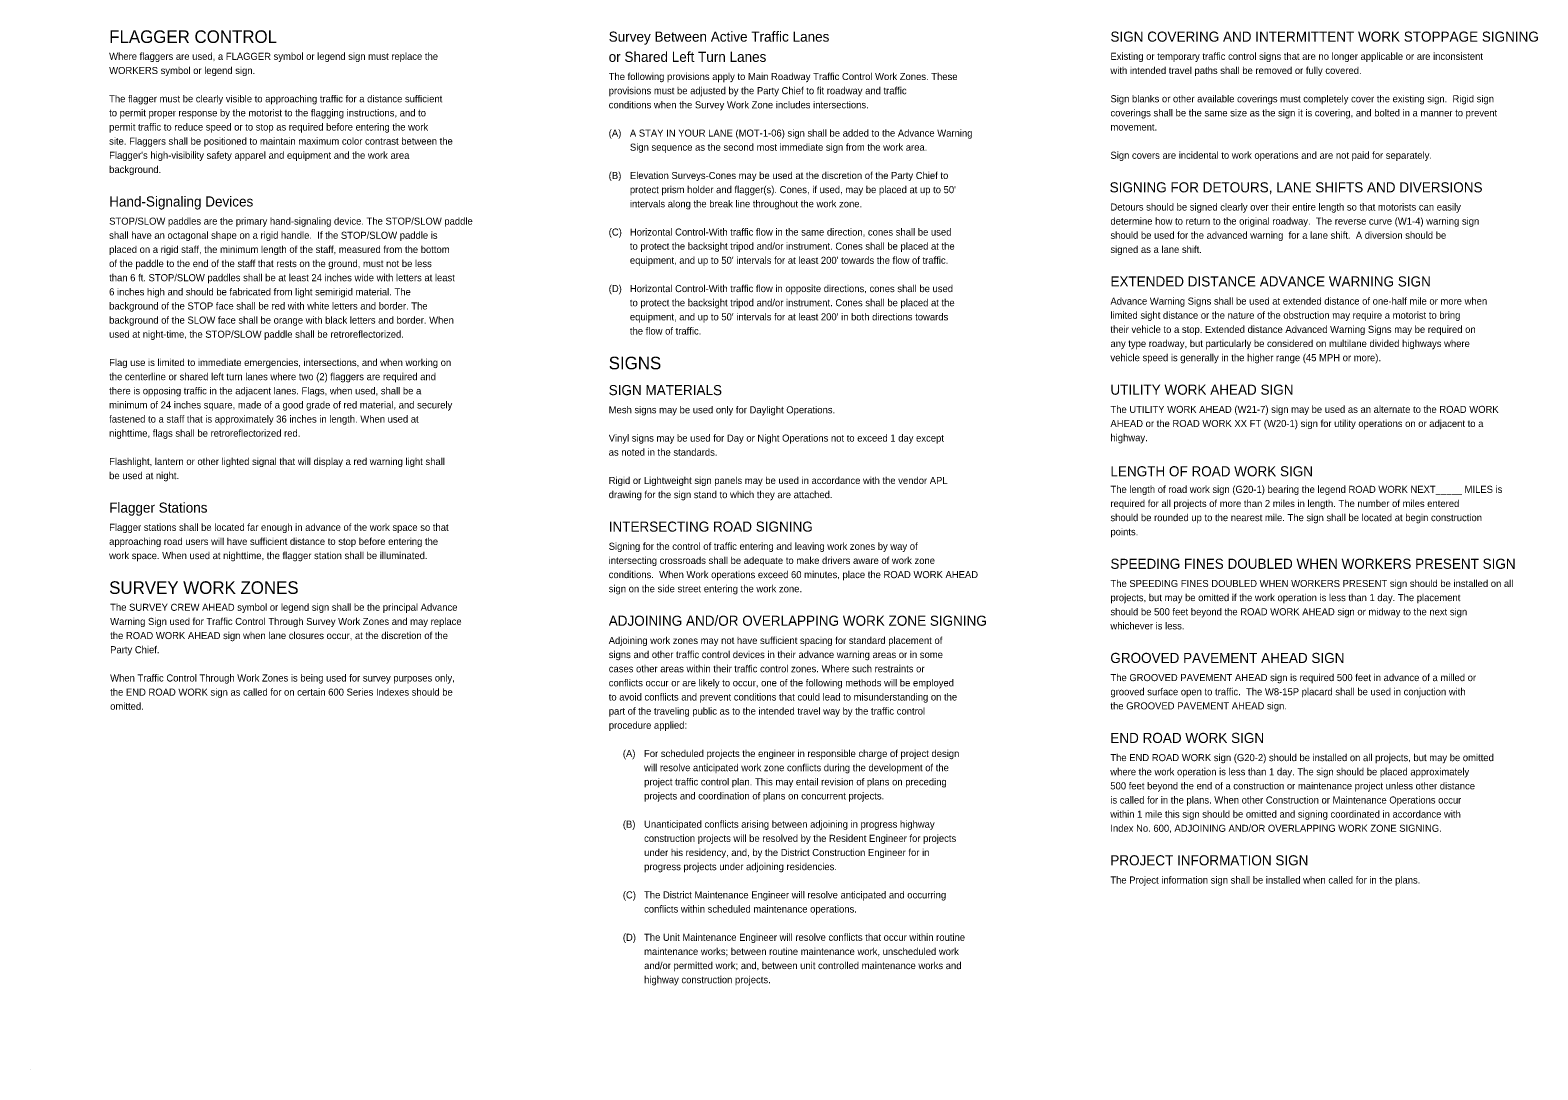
# Model space of a CAD drawing. Extents: x 10000 to 10746, y 10000 to 10515.
import ezdxf

# ---------------------------------------------------------------- set-up
doc = ezdxf.new("R2010")
doc.units = 0
doc.layers.add('Patterning', color=7, linetype='Continuous')
doc.layers.add('TextMisc', color=7, linetype='Continuous')

msp = doc.modelspace()

# ---------------------------------------------------------------- linework, layer by layer
at = {"layer": 'Patterning'}
msp.add_line((10000, 10000), (10000, 10000), dxfattribs=at)
msp.add_line((10000, 10000), (10000, 10000), dxfattribs=at)

# ---------------------------------------------------------------- texts
at = {"layer": 'TextMisc'}
for s, height, p in [('FLAGGER CONTROL', 6.25, (10039.11, 10508.47)), ('Survey Between Active Traffic Lanes', 5, (10286.45, 10509.1)), ('SIGN COVERING AND INTERMITTENT WORK STOPPAGE SIGNING', 5, (10534.87, 10509.1)), ('Where flaggers are used, a FLAGGER symbol or legend sign must replace the ', 3.5, (10039.11, 10500.1)), ('or Shared Left Turn Lanes', 5, (10286.45, 10499.1)), ('Existing or temporary traffic control signs that are no longer applicable or are inconsistent ', 3.5, (10534.87, 10500.1)), ('WORKERS symbol or legend sign.', 3.5, (10039.11, 10493.1)), ('with intended travel paths shall be removed or fully covered. ', 3.5, (10534.87, 10493.1)), ('The following provisions apply to Main Roadway Traffic Control Work Zones. These ', 3.5, (10286.45, 10490.1)), ('The flagger must be clearly visible to approaching traffic for a distance sufficient ', 3.5, (10039.11, 10479.1)), ('provisions must be adjusted by the Party Chief to fit roadway and traffic ', 3.5, (10286.45, 10483.1)), ('Sign blanks or other available coverings must completely cover the existing sign.  Rigid sign ', 3.5, (10534.87, 10479.1)), ('to permit proper response by the motorist to the flagging instructions, and to ', 3.5, (10039.11, 10472.1)), ('conditions when the Survey Work Zone includes intersections.', 3.5, (10286.45, 10476.1)), ('coverings shall be the same size as the sign it is covering, and bolted in a manner to prevent ', 3.5, (10534.87, 10472.1)), ('permit traffic to reduce speed or to stop as required before entering the work ', 3.5, (10039.11, 10465.1)), ('(A)', 3.5, (10286.45, 10462.1)), ('A STAY IN YOUR LANE (MOT-1-06) sign shall be added to the Advance Warning ', 3.5, (10296.95, 10462.1)), ('movement.', 3.5, (10534.87, 10465.1)), ('site. Flaggers shall be positioned to maintain maximum color contrast between the ', 3.5, (10039.11, 10458.1)), ('Sign sequence as the second most immediate sign from the work area.', 3.5, (10296.95, 10455.1)), ("Flagger's high-visibility safety apparel and equipment and the work area ", 3.5, (10039.11, 10451.1)), ('Sign covers are incidental to work operations and are not paid for separately.', 3.5, (10534.87, 10451.1)), ('background.', 3.5, (10039.11, 10444.1)), ('(B)', 3.5, (10286.45, 10441.1)), ('Elevation Surveys-Cones may be used at the discretion of the Party Chief to ', 3.5, (10296.95, 10441.1)), ("protect prism holder and flagger(s). Cones, if used, may be placed at up to 50'  ", 3.5, (10296.95, 10434.1)), ('SIGNING FOR DETOURS, LANE SHIFTS AND DIVERSIONS', 5, (10534.48, 10434.49)), ('Hand-Signaling Devices', 5, (10039.11, 10427.49)), ('intervals along the break line throughout the work zone.', 3.5, (10296.95, 10427.1)), ('Detours should be signed clearly over their entire length so that motorists can easily ', 3.5, (10534.87, 10425.49)), ('STOP/SLOW paddles are the primary hand-signaling device. The STOP/SLOW paddle ', 3.5, (10039.11, 10418.49)), ('determine how to return to the original roadway.  The reverse curve (W1-4) warning sign ', 3.5, (10534.87, 10418.49)), ('shall have an octagonal shape on a rigid handle.  If the STOP/SLOW paddle is ', 3.5, (10039.11, 10411.49)), ('(C)', 3.5, (10286.45, 10413.1)), ('Horizontal Control-With traffic flow in the same direction, cones shall be used ', 3.5, (10296.95, 10413.1)), ('should be used for the advanced warning  for a lane shift.  A diversion should be ', 3.5, (10534.87, 10411.49)), ('placed on a rigid staff, the minimum length of the staff, measured from the bottom ', 3.5, (10039.11, 10404.49)), ('to protect the backsight tripod and/or instrument. Cones shall be placed at the ', 3.5, (10296.95, 10406.1)), ('signed as a lane shift.', 3.5, (10534.87, 10404.49)), ('of the paddle to the end of the staff that rests on the ground, must not be less ', 3.5, (10039.11, 10397.49)), ("equipment, and up to 50' intervals for at least 200' towards the flow of traffic.", 3.5, (10296.95, 10399.1)), ('than 6 ft. STOP/SLOW paddles shall be at least 24 inches wide with letters at least ', 3.5, (10039.11, 10390.49)), ('EXTENDED DISTANCE ADVANCE WARNING SIGN', 5, (10534.87, 10387.89)), ('6 inches high and should be fabricated from light semirigid material. The ', 3.5, (10039.11, 10383.49)), ('(D)', 3.5, (10286.45, 10385.1)), ('Horizontal Control-With traffic flow in opposite directions, cones shall be used ', 3.5, (10296.95, 10385.1)), ('background of the STOP face shall be red with white letters and border. The ', 3.5, (10039.11, 10376.49)), ('to protect the backsight tripod and/or instrument. Cones shall be placed at the ', 3.5, (10296.95, 10378.1)), ('Advance Warning Signs shall be used at extended distance of one-half mile or more when ', 3.5, (10534.87, 10378.89)), ('background of the SLOW face shall be orange with black letters and border. When ', 3.5, (10039.11, 10369.49)), ("equipment, and up to 50' intervals for at least 200' in both directions towards ", 3.5, (10296.95, 10371.1)), ('limited sight distance or the nature of the obstruction may require a motorist to bring ', 3.5, (10534.87, 10371.89)), ('used at night-time, the STOP/SLOW paddle shall be retroreflectorized.', 3.5, (10039.11, 10362.49)), ('the flow of traffic.', 3.5, (10296.95, 10364.1)), ('their vehicle to a stop. Extended distance Advanced Warning Signs may be required on ', 3.5, (10534.87, 10364.89)), ('any type roadway, but particularly be considered on multilane divided highways where ', 3.5, (10534.87, 10357.89)), ('vehicle speed is generally in the higher range (45 MPH or more).', 3.5, (10534.87, 10350.89)), ('Flag use is limited to immediate emergencies, intersections, and when working on ', 3.5, (10039.11, 10348.49)), ('SIGNS', 6.25, (10286.45, 10346.87)), ('the centerline or shared left turn lanes where two (2) flaggers are required and ', 3.5, (10039.11, 10341.49)), ('SIGN MATERIALS', 5, (10286.45, 10334.08)), ('UTILITY WORK AHEAD SIGN', 5, (10534.87, 10334.29)), ('there is opposing traffic in the adjacent lanes. Flags, when used, shall be a ', 3.5, (10039.11, 10334.49)), ('fastened to a staff that is approximately 36 inches in length. When used at ', 3.5, (10039.11, 10320.49)), ('minimum of 24 inches square, made of a good grade of red material, and securely ', 3.5, (10039.11, 10327.49)), ('Mesh signs may be used only for Daylight Operations.', 3.5, (10286.45, 10325.08)), ('The UTILITY WORK AHEAD (W21-7) sign may be used as an alternate to the ROAD WORK ', 3.5, (10534.87, 10325.29)), ('nighttime, flags shall be retroreflectorized red.', 3.5, (10039.11, 10313.49)), ('AHEAD or the ROAD WORK XX FT (W20-1) sign for utility operations on or adjacent to a ', 3.5, (10534.87, 10318.29)), ('Vinyl signs may be used for Day or Night Operations not to exceed 1 day except ', 3.5, (10286.45, 10311.08)), ('highway.', 3.5, (10534.87, 10311.29)), ('Flashlight, lantern or other lighted signal that will display a red warning light shall ', 3.5, (10039.11, 10299.49)), ('as noted in the standards.', 3.5, (10286.45, 10304.08)), ('be used at night.', 3.5, (10039.11, 10292.49)), ('LENGTH OF ROAD WORK SIGN', 5, (10534.87, 10293.89)), ('drawing for the sign stand to which they are attached.', 3.5, (10286.45, 10283.08)), ('Rigid or Lightweight sign panels may be used in accordance with the vendor APL ', 3.5, (10286.45, 10290.08)), ('The length of road work sign (G20-1) bearing the legend ROAD WORK NEXT_____ MILES is ', 3.5, (10534.87, 10285.69)), ('Flagger Stations', 5, (10039.11, 10275.89)), ('required for all projects of more than 2 miles in length. The number of miles entered ', 3.5, (10534.87, 10278.69)), ('should be rounded up to the nearest mile. The sign shall be located at begin construction ', 3.5, (10534.87, 10271.69)), ('Flagger stations shall be located far enough in advance of the work space so that ', 3.5, (10039.11, 10266.89)), ('INTERSECTING ROAD SIGNING', 5, (10286.45, 10266.48)), ('points.', 3.5, (10534.87, 10264.69)), ('approaching road users will have sufficient distance to stop before entering the ', 3.5, (10039.11, 10259.89)), ('Signing for the control of traffic entering and leaving work zones by way of ', 3.5, (10286.45, 10257.48)), ('work space. When used at nighttime, the flagger station shall be illuminated.', 3.5, (10039.11, 10252.89)), ('intersecting crossroads shall be adequate to make drivers aware of work zone ', 3.5, (10286.45, 10250.48)), ('SPEEDING FINES DOUBLED WHEN WORKERS PRESENT SIGN', 5, (10534.87, 10248.08)), ('SURVEY WORK ZONES', 6.25, (10039.11, 10235.66)), ('conditions.  When Work operations exceed 60 minutes, place the ROAD WORK AHEAD ', 3.5, (10286.45, 10243.48)), ('The SPEEDING FINES DOUBLED WHEN WORKERS PRESENT sign should be installed on all ', 3.5, (10534.87, 10239.08)), ('sign on the side street entering the work zone.', 3.5, (10286.45, 10236.48)), ('projects, but may be omitted if the work operation is less than 1 day. The placement ', 3.5, (10534.87, 10232.08)), ('The SURVEY CREW AHEAD symbol or legend sign shall be the principal Advance ', 3.5, (10039.61, 10227.29)), ('should be 500 feet beyond the ROAD WORK AHEAD sign or midway to the next sign ', 3.5, (10534.87, 10225.08)), ('Warning Sign used for Traffic Control Through Survey Work Zones and may replace ', 3.5, (10039.61, 10220.29)), ('ADJOINING AND/OR OVERLAPPING WORK ZONE SIGNING', 5, (10286.45, 10219.88)), ('whichever is less. ', 3.5, (10534.87, 10218.08)), ('the ROAD WORK AHEAD sign when lane closures occur, at the discretion of the ', 3.5, (10039.61, 10213.29)), ('Adjoining work zones may not have sufficient spacing for standard placement of ', 3.5, (10286.45, 10210.88)), ('Party Chief. ', 3.5, (10039.61, 10206.29)), ('signs and other traffic control devices in their advance warning areas or in some ', 3.5, (10286.48, 10203.88)), ('GROOVED PAVEMENT AHEAD SIGN', 5, (10534.81, 10201.46)), ('cases other areas within their traffic control zones. Where such restraints or ', 3.5, (10286.48, 10196.88)), ('When Traffic Control Through Work Zones is being used for survey purposes only, ', 3.5, (10039.61, 10192.29)), ('conflicts occur or are likely to occur, one of the following methods will be employed ', 3.5, (10286.48, 10189.88)), ('The GROOVED PAVEMENT AHEAD sign is required 500 feet in advance of a milled or ', 3.5, (10534.87, 10192.48)), ('the END ROAD WORK sign as called for on certain 600 Series Indexes should be ', 3.5, (10039.61, 10185.29)), ('to avoid conflicts and prevent conditions that could lead to misunderstanding on the ', 3.5, (10286.48, 10182.88)), ('the GROOVED PAVEMENT AHEAD sign.', 3.5, (10534.87, 10178.48)), ('grooved surface open to traffic.  The W8-15P placard shall be used in conjuction with ', 3.5, (10534.87, 10185.48)), ('omitted.', 3.5, (10039.61, 10178.29)), ('part of the traveling public as to the intended travel way by the traffic control ', 3.5, (10286.48, 10175.88)), ('procedure applied:', 3.5, (10286.48, 10168.88)), ('END ROAD WORK SIGN', 5, (10534.81, 10161.86)), ('(A)', 3.5, (10293.45, 10154.88)), ('For scheduled projects the engineer in responsible charge of project design ', 3.5, (10303.95, 10154.88)), ('The END ROAD WORK sign (G20-2) should be installed on all projects, but may be omitted ', 3.5, (10534.81, 10152.86)), ('will resolve anticipated work zone conflicts during the development of the ', 3.5, (10303.98, 10147.88)), ('where the work operation is less than 1 day. The sign should be placed approximately ', 3.5, (10534.81, 10145.86)), ('project traffic control plan. This may entail revision of plans on preceding ', 3.5, (10303.98, 10140.88)), ('projects and coordination of plans on concurrent projects.', 3.5, (10303.98, 10133.88)), ('500 feet beyond the end of a construction or maintenance project unless other distance ', 3.5, (10534.81, 10138.86)), ('is called for in the plans. When other Construction or Maintenance Operations occur ', 3.5, (10534.81, 10131.86)), ('(B)', 3.5, (10293.45, 10119.88)), ('Unanticipated conflicts arising between adjoining in progress highway ', 3.5, (10303.95, 10119.88)), ('within 1 mile this sign should be omitted and signing coordinated in accordance with ', 3.5, (10534.81, 10124.86)), ('construction projects will be resolved by the Resident Engineer for projects ', 3.5, (10303.98, 10112.88)), ('Index No. 600, ADJOINING AND/OR OVERLAPPING WORK ZONE SIGNING.', 3.5, (10534.81, 10117.86)), ('under his residency, and, by the District Construction Engineer for in ', 3.5, (10303.98, 10105.88)), ('progress projects under adjoining residencies.', 3.5, (10303.98, 10098.88)), ('PROJECT INFORMATION SIGN', 5, (10534.81, 10101.25)), ('The Project information sign shall be installed when called for in the plans.', 3.5, (10534.81, 10092.25)), ('(C)', 3.5, (10293.45, 10084.88)), ('The District Maintenance Engineer will resolve anticipated and occurring ', 3.5, (10303.95, 10084.88)), ('conflicts within scheduled maintenance operations.', 3.5, (10303.98, 10077.88)), ('(D)', 3.5, (10293.45, 10063.88)), ('The Unit Maintenance Engineer will resolve conflicts that occur within routine ', 3.5, (10303.95, 10063.88)), ('maintenance works; between routine maintenance work, unscheduled work ', 3.5, (10303.98, 10056.88)), ('and/or permitted work; and, between unit controlled maintenance works and ', 3.5, (10303.98, 10049.88)), ('highway construction projects.', 3.5, (10303.98, 10042.88))]:
    msp.add_text(s, height=height, dxfattribs=at).set_placement(p)

doc.saveas('drawing.dxf')
